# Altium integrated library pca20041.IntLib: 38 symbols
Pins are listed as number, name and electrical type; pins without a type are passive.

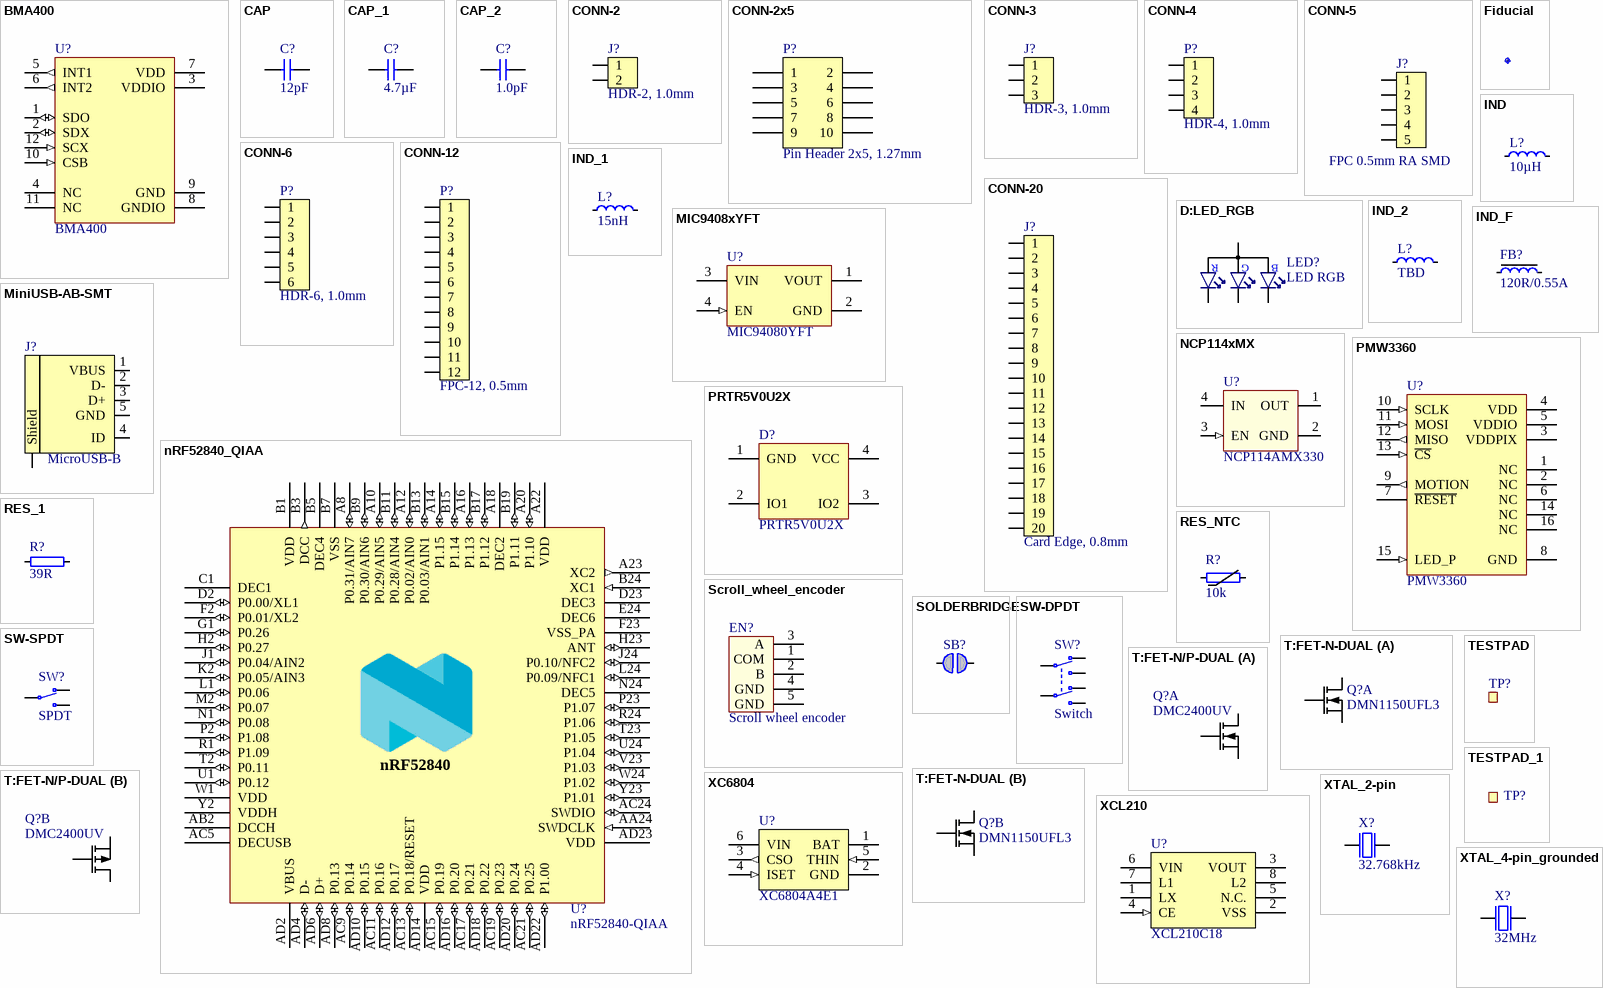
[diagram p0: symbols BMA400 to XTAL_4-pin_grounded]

## BMA400
designator U?
Digital, triaxial acceleration sensor; Manufacturer: Bosch; Artikkelnr Noca: N.A.
footprint PQFN50P200X200X100-12N_var
pins: 1 SDO (io), 2 SDX (io), 3 VDDIO (power), 4 NC, 5 INT1 (out), 6 INT2 (out), 7 VDD (power), 8 GNDIO (power), 9 GND (power), 10 CSB (in), 11 NC, 12 SCX (in)

## CAP
designator C?, comment 12pF
Capacitor, NP0, ±2%; Part Number: C0201-12p; Part number IPS: 00000007848; Note: 25V; Artikkelnr Noca: N.A.
footprint CAPC0603X03L_C
pins: 1, 2

## CAP_1
designator C?, comment 4.7µF
Capacitor, X7R, ±10%; Part Number: C0603-4µ7-6.3V-X7R; Manufacturer: Samsung; Manufacturer Part Number: CL10B475KQ8NQNC; Part number IPS: N.A.; Note: 6.3V; Artikkelnr Noca: 20039473
footprint CAPC1608X06L
pins: 1, 2

## CAP_2
designator C?, comment 1.0pF
Capacitor, NP0, ±0.1pF; Part Number: C0402-1.0p; Part number IPS: N.A.; Note: 50V; Artikkelnr Noca: 20029140
footprint CAPC1005X04L
pins: 1, 2

## CONN-2
designator J?, comment HDR-2, 1.0mm
1.0mm pitch top entry SMD wire to board connector; Part Number: BM02B-SRSS-TB; Manufacturer: JST; Note: JST, Header; Artikkelnr Noca: N.A.
footprint BM02B-SRSS-TB
pins: 1, 2

## CONN-2x5
designator P?, comment Pin Header 2x5, 1.27mm
Pin Header 2x5, 1.27mm (50mil), SMD, Keying Shroud; Part Number: Pin Header 2x5 SMD, 1.27mm, KS; Manufacturer: W-CON; Manufacturer Part Number: 3132-10MS0BK00R1; Part number IPS: N.A.; Artikkelnr Noca: 55010009
footprint HDR_2x5-SMD-1.27mm-K
pins: 1, 2, 3, 4, 5, 6, 7, 8, 9, 10

## CONN-3
designator J?, comment HDR-3, 1.0mm
1.0mm pitch top entry SMD wire to board connector; Part Number: BM03B-SRSS-TB; Manufacturer: JST; Note: JST, Header; Artikkelnr Noca: N.A.
footprint BM03B-SRSS-TB
pins: 1, 2, 3

## CONN-4
designator P?, comment HDR-4, 1.0mm
1.0mm pitch top entry SMD wire to board connector; Part Number: BM04B-SRSS-TB; Manufacturer: JST; Note: JST, Header; Artikkelnr Noca: N.A.
footprint BM04B-SRSS-TB
pins: 1, 2, 3, 4

## CONN-5
designator J?, comment FPC 0.5mm RA SMD
0.5mm FPC, 5P,Right Angle SMT,Double Contact,H=1.2mm,White, Tin plated; Part Number: FPC_05P-0.5mm-RA-SMD; Manufacturer: W-CON; Manufacturer Part Number: 5141-05RZDNWR01; Part number IPS: 00000007792; Artikkelnr Noca: 55010020
footprint FPC_05P-0.5mm-RA-SMD
pins: 1, 2, 3, 4, 5

## CONN-6
designator P?, comment HDR-6, 1.0mm
1.0mm pitch top entry SMD wire to board connector; Part Number: BM06B-SRSS-TB; Manufacturer: JST; Note: JST, Header; Artikkelnr Noca: N.A.
footprint BM06B-SRSS-TB
pins: 1, 2, 3, 4, 5, 6

## CONN-12
designator P?, comment FPC-12, 0.5mm
0.5mm pitch, bottom side contact, side entry SMD FPC connector; Part Number: 10051922-1210ELF; Manufacturer: FCI; Artikkelnr Noca: N.A.
footprint 10051922-1210ELF
pins: 1, 2, 3, 4, 5, 6, 7, 8, 9, 10, 11, 12

## CONN-20
designator J?, comment Card Edge, 0.8mm
0.8mm pitch, dual edge, right angle, SMD, card edge connector; Part Number: 10056847-101LF; Manufacturer: FCI; Artikkelnr Noca: N.A.
footprint 10056847-101LF
pins: 1, 2, 3, 4, 5, 6, 7, 8, 9, 10, 11, 12, 13, 14, 15, 16, 17, 18, 19, 20

## D:LED_RGB
designator LED?, comment LED RGB
Optek, Side mounted RGB 1204 SMD LED; Part Number: Led_RGB_Side; Manufacturer Part Number: OVSRRGBCC3; Artikkelnr Noca: N.A.
footprint L1204_RGB_SIDE
pins: 1 C_RED, 2 C_GREEN, 3 C_BLUE, 4 A

## Fiducial
designator Fid?, comment Fiducial mark  (value not drawn)
Part Number: Fid-Mark; Artikkelnr Noca: N.A.
footprint Fiducial

## IND
designator L?, comment 10µH
Inductor, 80mA, ±10%; Part Number: L0603-10µ; Manufacturer: Taiyo Yuden; Manufacturer Part Number: LBMF1608T100K; Part number IPS: 00000007794; Note: LBMF1608T100K 10µH 80mA 0603; Artikkelnr Noca: 33029314
footprint INDC1608X06L
pins: 1, 2

## IND_1
designator L?, comment 15nH
Inductor, 320mA, ±5%; Part Number: L0402-15n; Manufacturer: Taiyo Yuden; Manufacturer Part Number: HK100515NJ-T; Part number IPS: 00000001262; Note: High frequency chip inductor ±10%; Artikkelnr Noca: 33029323
footprint INDC1005X04L
pins: 1, 2

## IND_2
designator L?, comment TBD
Chip Inductor, TBD; Part Number: L0201-TBD; Artikkelnr Noca: N.A.
footprint INDC0603X03L_C
pins: 1, 2

## IND_F
designator FB?, comment 120R/0.55A
Ferrite Bead, 120 Ohm @ 100MHz, 500mA, 250 mOhm Max; Part Number: FB0402-120R@100M-500mA; Manufacturer: Murata; Manufacturer Part Number: BLM15AG121SN1D; Part number IPS: N.A.; Note: Chip EMIFIL Inductor Type Chip Ferrite Bead; Artikkelnr Noca: 33029317
footprint INDC1005X04L
pins: 1, 2

## MIC9408xYFT
designator U?, comment MIC94080YFT
2A High Side Load Switch, 67mΩ; Manufacturer: Microchip; Artikkelnr Noca: N.A.
footprint TMLF40P85X85X60-4N
pins: 1 VOUT (power), 2 GND (power), 3 VIN (power), 4 EN (in)

## MiniUSB-AB-SMT
designator J?, comment MicroUSB-B
MicroUSB-B-SMT; Part Number: USB-Micro-B-RA-SMD-PiP; Manufacturer: Allen Creations Corp.; Manufacturer Part Number: AJU55-BS2111-L; Part number IPS: 00000007790; Artikkelnr Noca: 55029020
footprint USB-Micro-B-RA-SMD-PiP
pins: 1 VBUS (power), 2 D-, 3 D+, 4 ID, 5 GND (power), 6 Shield (power)

## NCP114xMX
designator U?, comment NCP114AMX330
300 mA CMOS Low Dropout Regulator; Part Number: NCP114AMX330TBG; Manufacturer: ON Semiconductor; Artikkelnr Noca: N.A.
footprint UDFN65P100X100X60_HS-5N
pins: 1 OUT (power), 2 GND (power), 3 EN (in), 4 IN (power), 5 EPAD (power) hidden to GND

## nRF52840_QIAA
designator U?, comment nRF52840-QIAA
Multi-protocol Bluetooth Low Energy, IEEE 802.15.4, ANT and 2.4GHz proprietary system-on-chip; Part Number: nRF52840-QIAAC0; Manufacturer: Nordic Semiconductor; Part number IPS: N.A.; Artikkelnr Noca: 15079380
footprint AQFN50P700X700X85_HS-74N
pins: 74 GND (power) hidden to GND, A8 P0.31/AIN7 (io), A10 P0.29/AIN5 (io), A12 P0.02/AIN0 (io), A14 P1.15 (io), A16 P1.13 (io), A18 DEC2 (power), A20 P1.10 (io), A22 VDD (power), A23 XC2 (out), AA24 SWDCLK (in), AB2 DCCH (power), AC5 DECUSB (power), AC9 P0.14 (io), AC11 P0.16 (io), AC13 P0.18/RESET (io), AC15 P0.19 (io), AC17 P0.21 (io), AC19 P0.23 (io), AC21 P0.25 (io), AC24 SWDIO (io), AD2 VBUS (power), AD4 D- (io), AD6 D+ (io), AD8 P0.13 (io), AD10 P0.15 (io), AD12 P0.17 (io), AD14 VDD (power), AD16 P0.20 (io), AD18 P0.22 (io), AD20 P0.24 (io), AD22 P1.00 (io), AD23 VDD (power), B1 VDD (power), B3 DCC (out), B5 DEC4 (power), B7 VSS (power), B9 P0.30/AIN6 (io), B11 P0.28/AIN4 (io), B13 P0.03/AIN1 (io), B15 P1.14 (io), B17 P1.12 (io), B19 P1.11 (io), B24 XC1 (in), C1 DEC1 (power), D2 P0.00/XL1 (io), D23 DEC3 (power), E24 DEC6 (power), F2 P0.01/XL2 (io), F23 VSS_PA (power), G1 P0.26 (io), H2 P0.27 (io), H23 ANT (io), J1 P0.04/AIN2 (io), J24 P0.10/NFC2 (io), K2 P0.05/AIN3 (io), L1 P0.06 (io), L24 P0.09/NFC1 (io), M2 P0.07 (io), N1 P0.08 (io), N24 DEC5 (power), P2 P1.08 (io), P23 P1.07 (io), R1 P1.09 (io), R24 P1.06 (io), T2 P0.11 (io), T23 P1.05 (io), U1 P0.12 (io), U24 P1.04 (io), V23 P1.03 (io), W1 VDD (power), W24 P1.02 (io), Y2 VDDH (power), Y23 P1.01 (io)

## PMW3360
designator U?
Optical Gaming Navigation Sensor; Part Number: PMW3360DM-T2QU; Manufacturer: PixArt; Artikkelnr Noca: N.A.
footprint PMW3360DM-T2QU
pins: 1 NC, 2 NC, 3 VDDPIX (power), 4 VDD (power), 5 VDDIO (power), 6 NC, 7 ~{RESET} (power), 8 GND (power), 9 MOTION (out), 10 SCLK (in), 11 MOSI (in), 12 MISO (out), 13 ~{CS} (in), 14 NC, 15 LED_P (in), 16 NC

## PRTR5V0U2X
designator D?
Ultra low capacitance double rail-to-rail ESD protection diode; Manufacturer: NXP; Part number IPS: 00000009951; Artikkelnr Noca: 10069015
footprint SOT190P230X110-4L
pins: 1 GND, 2 IO1, 3 IO2, 4 VCC

## RES_1
designator R?, comment 39R
Resistor, ±1%, 0.05W; Part Number: R0201-39R; Note: Chip Res 1%; Artikkelnr Noca: N.A.
footprint RESC0603X03L_C
pins: 1, 2

## RES_NTC
designator R?, comment 10k
THERMISTOR 10K OHM NTC 0402 SMD; Part Number: NCP15XH103F03RC; Manufacturer: Murata; Part number IPS: 00000007808; Note: Chip Res 1%; Artikkelnr Noca: N.A.
footprint RESC1005X04L
pins: 1, 2

## Scroll_wheel_encoder
designator EN?, comment Scroll wheel encoder
Part Number: M01_Scroll_wheel_encoder; Artikkelnr Noca: N.A.
footprint M01_Scroll_Wheel_Encoder
pins: 1 COM, 2 B, 3 A, 4 GND, 5 GND

## SOLDERBRIDGE
designator SB?, comment Solderbridge  (value not drawn)  (no BOM)
Artikkelnr Noca: N.A.
footprint Solderbridge
pins: 1 0, 2 1

## SW-DPDT
designator SW?, comment Switch
SMD slide Switch (ON-ON); Part Number: Switch-Slide-Gull-Wing-DPDT-7.2x3.5mm; Manufacturer: C&K Components; Manufacturer Part Number: AYZ0202AGRLC; Artikkelnr Noca: N.A.
footprint Switch-Slide-Gull-Wing-DPDT-7.2x3.5mm
pins: 1 N.O-1, 2 COM-1, 3 N.C-1, 4 N.O-2, 5 COM-2, 6 N.C-2

## SW-SPDT
designator SW?, comment SPDT
Sub-miniature snap action switch; Part Number: SS0750300F130P1A; Manufacturer: E-Switch; Part number IPS: N.A.; Artikkelnr Noca: 51019120
footprint SS0750300F130P1A
pins: 1 N.C, 2 COM, 3 N.O

## T:FET-N-DUAL
designator Q?, comment DMN1150UFL3
Dual N-Channel FET; Manufacturer: Diodes Incorporated; Artikkelnr Noca: N.A.
footprint X2DFN35P100X130X35-6N
part A pins: 1 S1, 2 G1, 6 D1
part B pins: 3 D2, 4 S2, 5 G2

## T:FET-N/P-DUAL
designator Q?, comment DMC2400UV
Dual N & P Ch MOFET, 1.03A/0.7A, 480mOhm, 450mW; Manufacturer: Diodes Incorporated; Part number IPS: 00000007803; Note: Dual N & P Channel Digital FET; Artikkelnr Noca: N.A.
footprint SOTFL50P162X60-6N
part A pins: 1 S1, 2 G1, 6 D1
part B pins: 3 D2, 4 S2, 5 G2

## TESTPAD
designator TP?, comment Ø1.5mm,SMD  (value not drawn)  (no BOM)
1.0mm circular SMD testpad; Part Number: TP_SMD_Ø1.5MM; Manufacturer: Nordic Semiconductor; Artikkelnr Noca: N.A.
footprint TP_SMD_Ø1.5mm
pins: 1

## TESTPAD_1
designator TP?, comment TP  (value not drawn)  (no BOM)
Testpoint, through hole; Part Number: Testpoint TH; Artikkelnr Noca: N.A.
footprint TESTPAD-TH
pins: 1

## XC6804
designator U?, comment XC6804A4E1
One Cell Li-ion/Li-polymer Linear Charger IC with Battery Temperature Detection; Part Number: XC6804A4E14R-G; Manufacturer: Torex Semiconductor; Part number IPS: 00000007825; Artikkelnr Noca: N.A.
footprint USP-6EL
pins: 1 BAT (power), 2 GND (power), 3 CSO (out), 4 ISET (in), 5 THIN (in), 6 VIN (power), 7 GND (power) hidden to GND

## XCL210
designator U?, comment XCL210C18
1.8V 200MA INDUCTOR BUILT-IN PFM STEP; Manufacturer: Torex Semiconductor; Manufacturer Part Number: XCL210C181GR-G; Artikkelnr Noca: N.A.
footprint CL-2025
pins: 1 LX, 2 VSS (power), 3 VOUT (power), 4 CE (in), 5 N.C., 6 VIN (power), 7 L1, 8 L2, 9 VSS (power) hidden to GND

## XTAL_2-pin
designator X?, comment 32.768kHz
XTAL SMD 2012, 32.768kHz, 9pF, ±20ppm; Part Number: XTAL_SMD2012_32.768kHz_9pF_NDK; Manufacturer: NDK; Manufacturer Part Number: NX2012SA 32.768KHz  S1-4085-xx20-9; Note: XTAL SMD 32.768kHz; Artikkelnr Noca: N.A.
footprint XTAL_2012
pins: 1 inp, 2 out

## XTAL_4-pin_grounded
designator X?, comment 32MHz
XTAL SMD 2016, 32MHz, Cl=8pF, Total Tol: ±40ppm; Part Number: XTAL_SMD2016_32MHz_8pF_General; Note: XTAL SMD 32.000MHz; Artikkelnr Noca: N.A.
footprint BT-XTAL_2016
pins: 1 inp, 2 GND hidden to GND, 3 out, 4 GND hidden to GND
